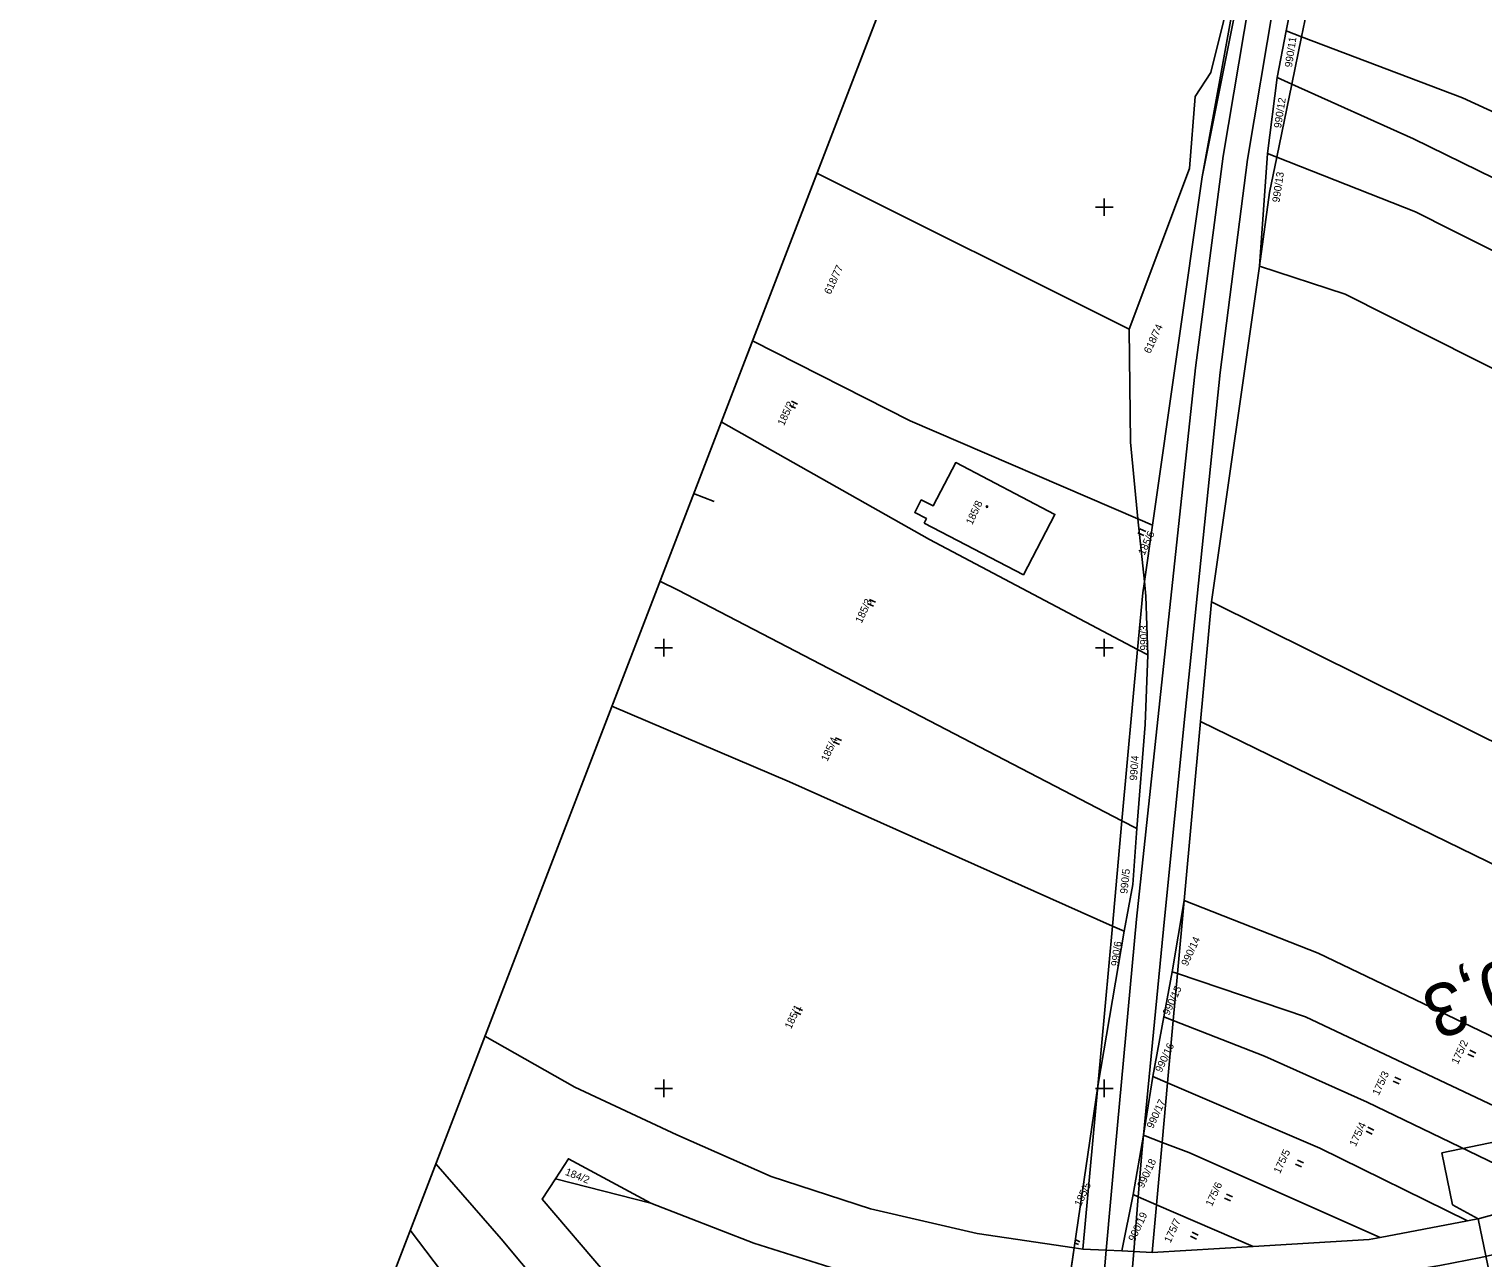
# Model space of a CAD drawing. Extents: x -755344 to -754412, y -1162670 to -1161477.
# Drawn here: x -755344.1 to -755014.1, y -1162238.5 to -1161959.6 of the extents above; entities that cross this region are included whole.
import ezdxf

# ---------------------------------------------------------------- set-up
doc = ezdxf.new("R2010")
doc.units = 0
for name, color, linetype in [('Formát', 7, 'Continuous'), ('hranice obvodu stavby', 7, 'Continuous'), ('Staniceni a namezniky', 7, 'Continuous'), ('Síť', 7, 'Continuous'), ('Vrstva 1', 7, 'Continuous'), ('Vrstva 53', 7, 'Continuous'), ('Vrstva 55', 7, 'Continuous'), ('Vrstva 56', 7, 'Continuous'), ('Vrstva 57', 7, 'Continuous'), ('Vrstva 58', 7, 'Continuous'), ('Vrstva 59', 7, 'Continuous')]:
    doc.layers.add(name, color=color, linetype=linetype)

msp = doc.modelspace()

# ---------------------------------------------------------------- linework, layer by layer
at = {"layer": 'Formát'}
for p, q in [((-755042.37, -1161673.02), (-755344.08, -1162456.97)), ((-755042.37, -1161673.02), (-755344.08, -1162456.97)), ((-755193.22, -1162065), (-755188.56, -1162066.79))]:
    msp.add_line(p, q, dxfattribs=at)
msp.add_lwpolyline([(-754488.01, -1161886.37), (-754789.71, -1162670.32), (-755344.08, -1162456.97), (-755042.37, -1161673.02)], close=True, dxfattribs=at)
msp.add_lwpolyline([(-754789.71, -1162670.32), (-754488.01, -1161886.37), (-755042.37, -1161673.02), (-755344.08, -1162456.97)], dxfattribs=at)
at = {"layer": 'hranice obvodu stavby'}
msp.add_lwpolyline([(-755010.64, -1162212), (-755023.37, -1162214.63), (-755020.94, -1162226.38), (-755020.94, -1162226.38), (-755020.94, -1162226.38), (-755015.16, -1162229.61), (-755012.14, -1162244.2), (-755017.04, -1162245.22), (-755015.23, -1162253.93), (-755005.62, -1162261.05)], dxfattribs=at)
at = {"layer": 'Síť'}
for points in [[(-755100, -1161998), (-755100, -1162000), (-755100, -1162002)], [(-755098, -1162000), (-755100, -1162000), (-755102, -1162000)], [(-755200, -1162098), (-755200, -1162100), (-755200, -1162102)], [(-755100, -1162098), (-755100, -1162100), (-755100, -1162102)], [(-755198, -1162100), (-755200, -1162100), (-755202, -1162100)], [(-755098, -1162100), (-755100, -1162100), (-755102, -1162100)], [(-755198, -1162200), (-755200, -1162200), (-755202, -1162200)], [(-755200, -1162198), (-755200, -1162200), (-755200, -1162202)], [(-755098, -1162200), (-755100, -1162200), (-755102, -1162200)], [(-755100, -1162198), (-755100, -1162200), (-755100, -1162202)]]:
    msp.add_lwpolyline(points, dxfattribs=at)
at = {"layer": 'Vrstva 1'}
msp.add_lwpolyline([(-755006.19, -1162236.46), (-755014.55, -1162238.36), (-755023.83, -1162240.18), (-755032.89, -1162241.66), (-755039.07, -1162242.52), (-755049.19, -1162243.63), (-755059.44, -1162244.4)], dxfattribs=at)
at = {"layer": 'Vrstva 53'}
msp.add_lwpolyline([(-755108.91, -1162250.29), (-755106.85, -1162236.16), (-755104.87, -1162236.45), (-755099.55, -1162236.71), (-755096.04, -1162236.88), (-755093.31, -1162237.02), (-755089.14, -1162237.23), (-755066.18, -1162235.85), (-755039.91, -1162234.27), (-755037.41, -1162233.8), (-755017.58, -1162230.07), (-755014.83, -1162229.55), (-754996.22, -1162224.35)], dxfattribs=at)
at = {"layer": 'Vrstva 55'}
for p, q in [((-755077.79, -1161993.12), (-755056.71, -1161887.12)), ((-755058.72, -1161960), (-755053.45, -1161933.51)), ((-755049.81, -1161934.92), (-755055.25, -1161961.32)), ((-755060.8, -1161970.61), (-755058.72, -1161960)), ((-755058.72, -1161960), (-755055.25, -1161961.32)), ((-755055.25, -1161961.32), (-755057.47, -1161972.1)), ((-755062.96, -1161987.84), (-755060.8, -1161970.61)), ((-755057.47, -1161972.1), (-755060.88, -1161988.66)), ((-755060.8, -1161970.61), (-755057.47, -1161972.1)), ((-755064.79, -1162013.41), (-755062.96, -1161987.84)), ((-755062.96, -1161987.84), (-755060.88, -1161988.66)), ((-755165.24, -1161992.28), (-755094.33, -1162027.67)), ((-755077.79, -1161993.12), (-755089.07, -1162072.18)), ((-755064.79, -1162013.41), (-755075.64, -1162089.56)), ((-755089.07, -1162072.18), (-755092.37, -1162070.76)), ((-755092.37, -1162070.76), (-755090.9, -1162084.97)), ((-755090.9, -1162084.97), (-755089.07, -1162072.18)), ((-755075.64, -1162089.56), (-755078.18, -1162116.73)), ((-755075.64, -1162089.56), (-754900.06, -1162176.77)), ((-755095.99, -1162139.26), (-755092.44, -1162100.39)), ((-755092.44, -1162100.39), (-755090.11, -1162101.62)), ((-755081.87, -1162157.32), (-755078.18, -1162116.73)), ((-755078.18, -1162116.73), (-754923.5, -1162192.2)), ((-755098.17, -1162163.16), (-755095.99, -1162139.26)), ((-755095.99, -1162139.26), (-755092.6, -1162141.02)), ((-755084.59, -1162173.51), (-755081.87, -1162157.32)), ((-755081.87, -1162157.32), (-755083.38, -1162173.92)), ((-755101.49, -1162199.47), (-755098.17, -1162163.16)), ((-755098.17, -1162163.16), (-755095.52, -1162164.34)), ((-755095.52, -1162164.34), (-755101.49, -1162199.47)), ((-755086.46, -1162183.76), (-755084.59, -1162173.51)), ((-755084.59, -1162173.51), (-755083.38, -1162173.92)), ((-755083.38, -1162173.92), (-755084.35, -1162184.59)), ((-755088.99, -1162197.29), (-755086.46, -1162183.76)), ((-755086.46, -1162183.76), (-755084.35, -1162184.59)), ((-755084.35, -1162184.59), (-755085.64, -1162198.73)), ((-755101.49, -1162199.47), (-755106.85, -1162236.16)), ((-755104.87, -1162236.45), (-755101.49, -1162199.47)), ((-755091.13, -1162210.63), (-755088.99, -1162197.29)), ((-755088.99, -1162197.29), (-755085.64, -1162198.73)), ((-755085.64, -1162198.73), (-755086.87, -1162212.23)), ((-755093.47, -1162224.09), (-755091.13, -1162210.63)), ((-755091.13, -1162210.63), (-755086.87, -1162212.23)), ((-755086.87, -1162212.23), (-755088.15, -1162226.38)), ((-755224.59, -1162220.51), (-755202.91, -1162226.05)), ((-755096.04, -1162236.88), (-755093.47, -1162224.09)), ((-755088.15, -1162226.38), (-755089.14, -1162237.23)), ((-755066.18, -1162235.85), (-755088.15, -1162226.38)), ((-755037.41, -1162233.8), (-755017.58, -1162230.07)), ((-755108.91, -1162250.29), (-755106.85, -1162236.16)), ((-755104.87, -1162236.45), (-755106.85, -1162236.16)), ((-755066.18, -1162235.85), (-755089.14, -1162237.23))]:
    msp.add_line(p, q, dxfattribs=at)
for points in [[(-755094.33, -1162027.67), (-755080.69, -1161991.19), (-755079.39, -1161974.89), (-755075.84, -1161969.41), (-755067.12, -1161934.32)], [(-755067.12, -1161934.32), (-755070.48, -1161952.7), (-755077.79, -1161993.12)], [(-755055.25, -1161961.32), (-755018.7, -1161975.2), (-754973.07, -1161996.16), (-754920.4, -1162024.65), (-754828.75, -1162070.02)], [(-755057.47, -1161972.1), (-755029.84, -1161984.47), (-754985.77, -1162006.08), (-754934.11, -1162033.82), (-754837.06, -1162081.94)], [(-755060.88, -1161988.66), (-755062.52, -1161996.64), (-755064.79, -1162013.41)], [(-755060.88, -1161988.66), (-755029.34, -1162001.05), (-755021.14, -1162005.19), (-754997.44, -1162017.02), (-754900.68, -1162066.68), (-754845.66, -1162094.27)], [(-754858.37, -1162113.93), (-755045.32, -1162019.78), (-755064.79, -1162013.41)], [(-755094.33, -1162027.67), (-755094.07, -1162053.35), (-755092.37, -1162070.76)], [(-755092.37, -1162070.76), (-755144.04, -1162048.5), (-755179.88, -1162030.34)], [(-755186.95, -1162048.7), (-755139.71, -1162075.43), (-755092.44, -1162100.39)], [(-755140.9, -1162071.68), (-755140.39, -1162070.68), (-755143.03, -1162069.3), (-755141.54, -1162066.44), (-755138.88, -1162067.81), (-755133.73, -1162057.97), (-755111.2, -1162069.74), (-755118.35, -1162083.41), (-755140.9, -1162071.68)], [(-755200.88, -1162084.9), (-755196.74, -1162086.92), (-755095.99, -1162139.26)], [(-755092.44, -1162100.39), (-755091.26, -1162087.49), (-755090.9, -1162084.97)], [(-755090.9, -1162084.97), (-755090.56, -1162088.25), (-755090.11, -1162101.62)], [(-755090.11, -1162101.62), (-755090.73, -1162117.44), (-755092.6, -1162141.02)], [(-755098.17, -1162163.16), (-755171.47, -1162130.42), (-755211.78, -1162113.21)], [(-755092.6, -1162141.02), (-755093.55, -1162153.72), (-755095.52, -1162164.34)], [(-755081.87, -1162157.32), (-755051.44, -1162169.33), (-755012.93, -1162187.79), (-754964.26, -1162213.49)], [(-755083.38, -1162173.92), (-755054.32, -1162183.78), (-755003.14, -1162207.94), (-754980.63, -1162219.28)], [(-755084.35, -1162184.59), (-755063.67, -1162192.69), (-755040.35, -1162203.08), (-754996.22, -1162224.35)], [(-755240.62, -1162188.15), (-755220.18, -1162199.71), (-755197.03, -1162210.54), (-755175.66, -1162219.97), (-755153.09, -1162227.31), (-755128.84, -1162232.93), (-755106.85, -1162236.16)], [(-755085.64, -1162198.73), (-755051.1, -1162213.59), (-755017.58, -1162230.07)], [(-755086.87, -1162212.23), (-755080.8, -1162214.51), (-755037.41, -1162233.8)], [(-755224.59, -1162220.51), (-755221.65, -1162215.97), (-755202.91, -1162226.05)], [(-755251.78, -1162217.14), (-755236.92, -1162234.12), (-755218.86, -1162255.78), (-755201.65, -1162278.82), (-755185.6, -1162302.84), (-755168.69, -1162327.53), (-755155.26, -1162350.62), (-755154.66, -1162351.82), (-755141.68, -1162377.77), (-755128.84, -1162403.34)], [(-755224.59, -1162220.51), (-755227.6, -1162225.16), (-755213.03, -1162242.21), (-755197.95, -1162261.69), (-755179.66, -1162287.01), (-755159.89, -1162316.68), (-755155.21, -1162323.55), (-755152.98, -1162327.62)], [(-755140.31, -1162246.01), (-755156.59, -1162242.36), (-755179.53, -1162235.08), (-755202.91, -1162226.05)], [(-755093.47, -1162224.09), (-755092.31, -1162224.59), (-755088.15, -1162226.38)], [(-755017.58, -1162230.07), (-755014.83, -1162229.55), (-754996.22, -1162224.35)], [(-755257.56, -1162232.16), (-755228.92, -1162270), (-755211.8, -1162300.42), (-755208.54, -1162317.82)], [(-755104.87, -1162236.45), (-755099.55, -1162236.71), (-755096.04, -1162236.88)], [(-755066.18, -1162235.85), (-755039.91, -1162234.27), (-755037.41, -1162233.8)], [(-755096.04, -1162236.88), (-755093.31, -1162237.02), (-755089.14, -1162237.23)]]:
    msp.add_lwpolyline(points, dxfattribs=at)
at = {"layer": 'Vrstva 56'}
for p, q in [((-755067.04, -1161952.84), (-755073.02, -1161988.39)), ((-755067.48, -1161989.17), (-755061.51, -1161953.6)), ((-755073.02, -1161988.39), (-755079.28, -1162036.49)), ((-755073.71, -1162037.5), (-755067.48, -1161989.17)), ((-755079.28, -1162036.49), (-755087.37, -1162112.06)), ((-755081.63, -1162114.72), (-755073.71, -1162037.5)), ((-755087.37, -1162112.06), (-755092.67, -1162161.58)), ((-755086.32, -1162161.53), (-755081.63, -1162114.72)), ((-755092.67, -1162161.58), (-755097.54, -1162214.06)), ((-755091.13, -1162210.63), (-755086.32, -1162161.53)), ((-755091.52, -1162214.66), (-755091.13, -1162210.63)), ((-755097.54, -1162214.06), (-755099.55, -1162236.71)), ((-755092.31, -1162224.59), (-755091.52, -1162214.66)), ((-755093.31, -1162237.02), (-755092.31, -1162224.59)), ((-755099.55, -1162236.71), (-755100.18, -1162243.88)), ((-755093.88, -1162244.12), (-755093.31, -1162237.02))]:
    msp.add_line(p, q, dxfattribs=at)
at = {"layer": 'Vrstva 58'}
for p, q in [((-755170.07, -1162045.58), (-755171.43, -1162044.95)), ((-755169.64, -1162044.68), (-755171, -1162044.04)), ((-755091.04, -1162074.54), (-755092.4, -1162073.91)), ((-755090.61, -1162073.64), (-755091.97, -1162073)), ((-755152.38, -1162090.57), (-755153.74, -1162089.94)), ((-755151.95, -1162089.67), (-755153.31, -1162089.03)), ((-755160.08, -1162121.96), (-755161.44, -1162121.33)), ((-755159.65, -1162121.06), (-755161.01, -1162120.42)), ((-755168.93, -1162183.21), (-755170.29, -1162182.58)), ((-755168.5, -1162182.31), (-755169.86, -1162181.67)), ((-755016.1, -1162192.86), (-755017.46, -1162192.23)), ((-755015.67, -1162191.96), (-755017.03, -1162191.32)), ((-755033.1, -1162198.97), (-755034.46, -1162198.34)), ((-755032.67, -1162198.07), (-755034.03, -1162197.43)), ((-755039.22, -1162210.35), (-755040.58, -1162209.72)), ((-755038.79, -1162209.45), (-755040.15, -1162208.81)), ((-755054.82, -1162216.9), (-755056.18, -1162216.26)), ((-755055.25, -1162217.8), (-755056.61, -1162217.17)), ((-755071.34, -1162225.53), (-755072.7, -1162224.9)), ((-755070.91, -1162224.63), (-755072.27, -1162223.99)), ((-755079.11, -1162234.18), (-755080.47, -1162233.55)), ((-755078.69, -1162233.28), (-755080.05, -1162232.64)), ((-755105.85, -1162235.42), (-755106.77, -1162235)), ((-755105.57, -1162234.81), (-755106.48, -1162234.39))]:
    msp.add_line(p, q, dxfattribs=at)
at = {"layer": 'Vrstva 59'}
msp.add_circle((-755126.61, -1162067.97), 0.175, dxfattribs=at)

# ---------------------------------------------------------------- texts
at = {"layer": 'Staniceni a namezniky'}
msp.add_text('0,3', height=12, rotation=201.4151, dxfattribs=at).set_placement((-755007.99, -1162169.85))
at = {"layer": 'Vrstva 57'}
for s, rotation, p in [('990/11', 81.5688, (-755057.4, -1161968.36)), ('990/12', 81.0541, (-755059.88, -1161982.15)), ('990/13', 81.364, (-755060.25, -1161999)), ('618/77', 65, (-755162.17, -1162019.94)), ('618/74', 65, (-755089.6, -1162033.36)), ('185/2', 65, (-755172.74, -1162049.74)), ('185/8', 65, (-755129.99, -1162072.24)), ('185/6', 65, (-755090.91, -1162079.15)), ('185/3', 65, (-755155.09, -1162094.54)), ('990/3', 91.0032, (-755090.16, -1162100.59)), ('185/4', 65, (-755162.87, -1162125.93)), ('990/4', 85.6611, (-755092.6, -1162130.17)), ('990/5', 84.0269, (-755094.77, -1162155.89)), ('990/6', 82.2866, (-755096.83, -1162172.35)), ('990/14', 65, (-755081.13, -1162172.37)), ('990/15', 65, (-755085.32, -1162183.55)), ('185/1', 65, (-755171.11, -1162186.65)), ('990/16', 65, (-755087.03, -1162196.5)), ('175/2', 65, (-755019.76, -1162194.66)), ('175/3', 65, (-755037.72, -1162201.74)), ('990/17', 65, (-755088.97, -1162209.27)), ('175/4', 65, (-755042.93, -1162213.32)), ('175/5', 65, (-755060.14, -1162219.47)), ('990/18', 65, (-755091.11, -1162222.75)), ('184/2', 338.4561, (-755222.53, -1162219.57)), ('185/5', 65, (-755105.35, -1162226.93)), ('175/6', 65, (-755075.58, -1162226.91)), ('990/19', 65, (-755093.12, -1162234.88)), ('175/7', 65, (-755084.99, -1162235.18))]:
    msp.add_text(s, height=1.7, rotation=rotation, dxfattribs=at).set_placement(p)

doc.saveas('drawing.dxf')
